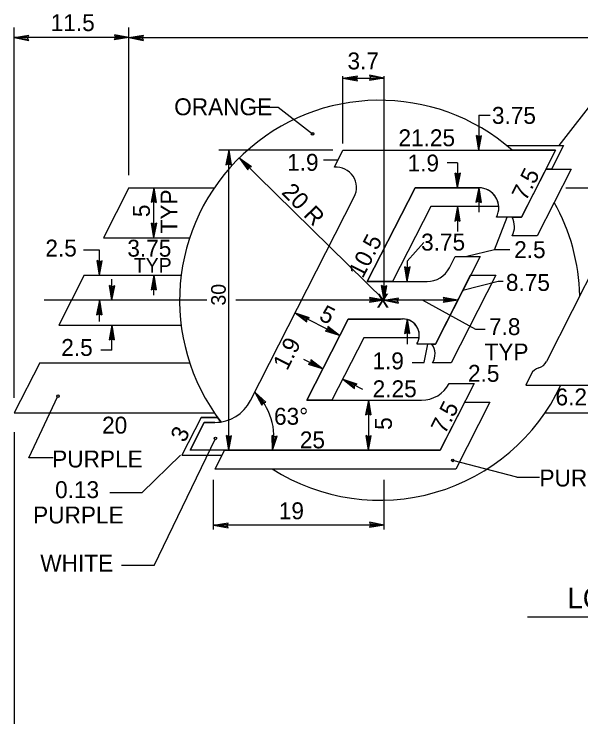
# Model space of a CAD drawing. Extents: x 10268197 to 10269179, y 2141503 to 2142677.
# Drawn here: x 10268597.1 to 10268620.55, y 2142238.8 to 2142268.18 of the extents above; entities that cross this region are included whole.
import ezdxf

# ---------------------------------------------------------------- set-up
doc = ezdxf.new("R2010")
doc.units = 0
for name, color, linetype in [('1', 7, 'Continuous'), ('2', 7, 'Continuous'), ('21', 7, 'Continuous'), ('3', 7, 'Continuous')]:
    doc.layers.add(name, color=color, linetype=linetype)

msp = doc.modelspace()

# ---------------------------------------------------------------- linework, layer by layer
at = {"layer": '1'}
for p, q in [((10268597.104, 2142252.29), (10268597.104, 2142267.627)), ((10268601.85, 2142261.513), (10268601.85, 2142267.627)), ((10268601.85, 2142267.213), (10268597.104, 2142267.213)), ((10268601.85, 2142267.213), (10268602.455, 2142267.309)), ((10268601.85, 2142267.213), (10268602.43, 2142267.254)), ((10268601.85, 2142267.213), (10268627.004, 2142267.213)), ((10268601.85, 2142267.213), (10268602.452, 2142267.097)), ((10268601.85, 2142267.213), (10268602.429, 2142267.153)), ((10268602.408, 2142267.204), (10268602.455, 2142267.309)), ((10268602.452, 2142267.097), (10268602.408, 2142267.204)), ((10268610.711, 2142265.538), (10268611.317, 2142265.634)), ((10268610.711, 2142262.832), (10268610.711, 2142265.61)), ((10268610.711, 2142265.538), (10268611.291, 2142265.578)), ((10268610.711, 2142265.538), (10268612.409, 2142265.538)), ((10268610.711, 2142265.538), (10268611.313, 2142265.422)), ((10268610.711, 2142265.538), (10268611.289, 2142265.478)), ((10268611.268, 2142265.528), (10268611.317, 2142265.634)), ((10268611.313, 2142265.422), (10268611.268, 2142265.528)), ((10268612.409, 2142256.338), (10268612.409, 2142265.61)), ((10268619.662, 2142262.748), (10268621.688, 2142265.366)), ((10268607.088, 2142264.329), (10268608.025, 2142264.329)), ((10268608.025, 2142264.329), (10268609.453, 2142263.226)), ((10268616.331, 2142263.999), (10268616.331, 2142262.548)), ((10268616.331, 2142263.999), (10268616.799, 2142263.999)), ((10268616.331, 2142262.548), (10268616.235, 2142263.154)), ((10268616.341, 2142263.105), (10268616.235, 2142263.154)), ((10268616.331, 2142262.548), (10268616.291, 2142263.128)), ((10268616.331, 2142262.548), (10268616.448, 2142263.149)), ((10268616.331, 2142262.548), (10268616.392, 2142263.127)), ((10268616.448, 2142263.149), (10268616.341, 2142263.105)), ((10268610.297, 2142262.548), (10268605.572, 2142262.548)), ((10268605.985, 2142262.548), (10268605.869, 2142261.947)), ((10268605.985, 2142262.548), (10268605.925, 2142261.97)), ((10268605.985, 2142250.127), (10268605.985, 2142262.548)), ((10268605.985, 2142262.548), (10268606.081, 2142261.942)), ((10268605.985, 2142262.548), (10268606.026, 2142261.968)), ((10268612.409, 2142256.338), (10268606.421, 2142262.237)), ((10268606.421, 2142262.237), (10268606.919, 2142261.881)), ((10268606.421, 2142262.237), (10268606.767, 2142261.732)), ((10268606.421, 2142262.237), (10268606.791, 2142261.788)), ((10268606.421, 2142262.237), (10268606.862, 2142261.859)), ((10268605.869, 2142261.947), (10268605.976, 2142261.991)), ((10268605.976, 2142261.991), (10268606.081, 2142261.942)), ((10268610.5, 2142262.134), (10268609.911, 2142262.134)), ((10268615.452, 2142262.03), (10268615.021, 2142262.03)), ((10268615.452, 2142262.03), (10268615.452, 2142260.995)), ((10268606.767, 2142261.732), (10268606.811, 2142261.839)), ((10268606.811, 2142261.839), (10268606.919, 2142261.881)), ((10268615.452, 2142260.995), (10268615.356, 2142261.6)), ((10268615.461, 2142261.553), (10268615.356, 2142261.6)), ((10268615.452, 2142260.995), (10268615.569, 2142261.597)), ((10268615.569, 2142261.597), (10268615.461, 2142261.553)), ((10268618.098, 2142259.779), (10268619.114, 2142261.772)), ((10268620.16, 2142261.772), (10268618.749, 2142259.005)), ((10268619.114, 2142261.772), (10268620.16, 2142261.772)), ((10268615.452, 2142260.995), (10268615.411, 2142261.575)), ((10268615.452, 2142260.995), (10268615.512, 2142261.574)), ((10268602.886, 2142260.995), (10268602.769, 2142260.394)), ((10268602.886, 2142260.995), (10268602.825, 2142260.417)), ((10268602.886, 2142258.925), (10268602.886, 2142260.995)), ((10268602.886, 2142260.995), (10268602.982, 2142260.39)), ((10268602.886, 2142260.995), (10268602.926, 2142260.416)), ((10268611.715, 2142257.114), (10268613.693, 2142260.995)), ((10268613.693, 2142260.995), (10268616.331, 2142260.995)), ((10268616.331, 2142260.995), (10268616.214, 2142260.394)), ((10268616.331, 2142260.995), (10268616.27, 2142260.417)), ((10268616.331, 2142260.995), (10268616.427, 2142260.39)), ((10268616.331, 2142260.995), (10268616.372, 2142260.416)), ((10268616.331, 2142260.995), (10268616.331, 2142259.984)), ((10268602.769, 2142260.394), (10268602.876, 2142260.438)), ((10268602.876, 2142260.438), (10268602.982, 2142260.39)), ((10268616.214, 2142260.394), (10268616.321, 2142260.438)), ((10268616.321, 2142260.438), (10268616.427, 2142260.39)), ((10268614.343, 2142260.219), (10268612.761, 2142257.114)), ((10268617.158, 2142260.219), (10268614.343, 2142260.219)), ((10268615.452, 2142260.219), (10268615.335, 2142259.618)), ((10268615.452, 2142260.219), (10268615.391, 2142259.64)), ((10268615.452, 2142260.219), (10268615.452, 2142259.184)), ((10268615.452, 2142260.219), (10268615.548, 2142259.614)), ((10268615.452, 2142260.219), (10268615.493, 2142259.64)), ((10268615.335, 2142259.618), (10268615.443, 2142259.661)), ((10268615.443, 2142259.661), (10268615.548, 2142259.614)), ((10268616.976, 2142258.427), (10268617.507, 2142259.781)), ((10268617.713, 2142259.779), (10268618.098, 2142259.779)), ((10268602.886, 2142258.925), (10268602.789, 2142259.53)), ((10268602.895, 2142259.483), (10268602.789, 2142259.53)), ((10268602.886, 2142258.925), (10268602.844, 2142259.505)), ((10268602.886, 2142258.925), (10268603.002, 2142259.527)), ((10268602.886, 2142258.925), (10268602.946, 2142259.504)), ((10268603.002, 2142259.527), (10268602.895, 2142259.483)), ((10268618.749, 2142259.005), (10268617.714, 2142259.005)), ((10268614.056, 2142258.726), (10268613.374, 2142257.956)), ((10268600.634, 2142258.408), (10268599.978, 2142258.412)), ((10268600.634, 2142257.373), (10268600.634, 2142258.408)), ((10268616.976, 2142258.427), (10268615.837, 2142258.149)), ((10268617.619, 2142258.427), (10268616.976, 2142258.427)), ((10268600.634, 2142257.373), (10268600.538, 2142257.978)), ((10268600.643, 2142257.93), (10268600.538, 2142257.978)), ((10268600.634, 2142257.373), (10268600.593, 2142257.952)), ((10268600.634, 2142257.373), (10268600.75, 2142257.974)), ((10268600.634, 2142257.373), (10268600.694, 2142257.951)), ((10268600.75, 2142257.974), (10268600.643, 2142257.93)), ((10268613.374, 2142257.956), (10268613.374, 2142257.114)), ((10268613.374, 2142257.114), (10268613.277, 2142257.719)), ((10268613.383, 2142257.671), (10268613.277, 2142257.719)), ((10268613.374, 2142257.114), (10268613.333, 2142257.693)), ((10268613.374, 2142257.114), (10268613.49, 2142257.716)), ((10268613.374, 2142257.114), (10268613.434, 2142257.692)), ((10268613.49, 2142257.716), (10268613.383, 2142257.671)), ((10268601.151, 2142256.338), (10268601.151, 2142257.217)), ((10268602.886, 2142257.373), (10268602.769, 2142256.771)), ((10268602.886, 2142257.373), (10268602.825, 2142256.794)), ((10268602.886, 2142256.545), (10268602.886, 2142257.373)), ((10268602.886, 2142257.373), (10268602.982, 2142256.767)), ((10268602.886, 2142257.373), (10268602.926, 2142256.793)), ((10268614.542, 2142254.526), (10268615.993, 2142257.373)), ((10268617.038, 2142257.373), (10268615.192, 2142253.75)), ((10268615.993, 2142257.373), (10268617.038, 2142257.373)), ((10268601.151, 2142256.338), (10268601.055, 2142256.942)), ((10268601.16, 2142256.895), (10268601.055, 2142256.942)), ((10268601.151, 2142256.338), (10268601.111, 2142256.917)), ((10268601.151, 2142256.338), (10268601.268, 2142256.939)), ((10268601.151, 2142256.338), (10268601.212, 2142256.916)), ((10268601.268, 2142256.939), (10268601.16, 2142256.895)), ((10268612.761, 2142257.114), (10268611.715, 2142257.114)), ((10268612.409, 2142256.338), (10268612.312, 2142256.942)), ((10268612.418, 2142256.895), (10268612.312, 2142256.942)), ((10268612.409, 2142256.338), (10268612.368, 2142256.917)), ((10268612.409, 2142256.338), (10268612.525, 2142256.939)), ((10268612.409, 2142256.338), (10268612.469, 2142256.916)), ((10268612.525, 2142256.939), (10268612.418, 2142256.895)), ((10268617.131, 2142257.115), (10268615.668, 2142256.735)), ((10268617.337, 2142257.115), (10268617.131, 2142257.115)), ((10268602.769, 2142256.771), (10268602.876, 2142256.815)), ((10268602.876, 2142256.815), (10268602.982, 2142256.767)), ((10268605.082, 2142256.338), (10268598.348, 2142256.338)), ((10268600.634, 2142256.338), (10268600.517, 2142255.736)), ((10268600.634, 2142256.338), (10268600.573, 2142255.759)), ((10268600.634, 2142255.458), (10268600.634, 2142256.338)), ((10268600.634, 2142256.338), (10268600.73, 2142255.732)), ((10268600.634, 2142256.338), (10268600.674, 2142255.758)), ((10268612.409, 2142256.338), (10268606.276, 2142256.338)), ((10268611.851, 2142256.347), (10268611.803, 2142256.242)), ((10268612.409, 2142256.338), (10268611.803, 2142256.242)), ((10268612.409, 2142256.338), (10268611.807, 2142256.454)), ((10268611.807, 2142256.454), (10268611.851, 2142256.347)), ((10268612.409, 2142256.338), (10268611.829, 2142256.297)), ((10268612.409, 2142256.338), (10268611.83, 2142256.398)), ((10268612.409, 2142256.338), (10268613.013, 2142256.433)), ((10268612.409, 2142256.338), (10268612.988, 2142256.378)), ((10268615.466, 2142256.338), (10268612.409, 2142256.338)), ((10268612.409, 2142256.338), (10268613.01, 2142256.221)), ((10268612.409, 2142256.338), (10268612.987, 2142256.277)), ((10268612.966, 2142256.328), (10268613.013, 2142256.433)), ((10268613.01, 2142256.221), (10268612.966, 2142256.328)), ((10268616.205, 2142255.132), (10268614.001, 2142256.338)), ((10268614.908, 2142256.347), (10268614.86, 2142256.242)), ((10268615.466, 2142256.338), (10268614.86, 2142256.242)), ((10268615.466, 2142256.338), (10268614.864, 2142256.454)), ((10268614.864, 2142256.454), (10268614.908, 2142256.347)), ((10268615.466, 2142256.338), (10268614.886, 2142256.297)), ((10268615.466, 2142256.338), (10268614.887, 2142256.398)), ((10268600.517, 2142255.736), (10268600.624, 2142255.78)), ((10268600.624, 2142255.78), (10268600.73, 2142255.732)), ((10268610.574, 2142254.873), (10268608.729, 2142255.814)), ((10268608.729, 2142255.814), (10268609.312, 2142255.624)), ((10268608.729, 2142255.814), (10268609.213, 2142255.437)), ((10268608.729, 2142255.814), (10268609.217, 2142255.498)), ((10268608.729, 2142255.814), (10268609.264, 2142255.587)), ((10268609.21, 2142252.198), (10268610.925, 2142255.561)), ((10268609.213, 2142255.437), (10268609.222, 2142255.552)), ((10268609.222, 2142255.552), (10268609.312, 2142255.624)), ((10268610.925, 2142255.561), (10268613.098, 2142255.554)), ((10268613.374, 2142255.561), (10268613.257, 2142254.96)), ((10268613.374, 2142255.561), (10268613.313, 2142254.983)), ((10268613.374, 2142255.561), (10268613.47, 2142254.956)), ((10268613.374, 2142255.561), (10268613.414, 2142254.982)), ((10268613.374, 2142255.561), (10268613.374, 2142254.526)), ((10268601.151, 2142255.302), (10268601.035, 2142254.701)), ((10268601.151, 2142255.302), (10268601.091, 2142254.724)), ((10268601.151, 2142254.267), (10268601.151, 2142255.302)), ((10268601.151, 2142255.302), (10268601.247, 2142254.697)), ((10268601.151, 2142255.302), (10268601.192, 2142254.723)), ((10268610.082, 2142255.135), (10268609.991, 2142255.063)), ((10268610.091, 2142255.251), (10268610.082, 2142255.135)), ((10268610.574, 2142254.873), (10268610.086, 2142255.19)), ((10268610.574, 2142254.873), (10268610.091, 2142255.251)), ((10268616.59, 2142255.132), (10268616.205, 2142255.132)), ((10268610.574, 2142254.873), (10268609.991, 2142255.063)), ((10268610.574, 2142254.873), (10268610.039, 2142255.1)), ((10268613.257, 2142254.96), (10268613.364, 2142255.004)), ((10268613.364, 2142255.004), (10268613.47, 2142254.956)), ((10268601.035, 2142254.701), (10268601.142, 2142254.745)), ((10268601.142, 2142254.745), (10268601.247, 2142254.697)), ((10268611.573, 2142254.783), (10268610.256, 2142252.198)), ((10268613.859, 2142254.775), (10268611.573, 2142254.783)), ((10268601.151, 2142254.267), (10268600.693, 2142254.271)), ((10268614.065, 2142253.763), (10268614.221, 2142254.526)), ((10268614.379, 2142254.526), (10268614.542, 2142254.526)), ((10268609.869, 2142253.491), (10268609.088, 2142253.889)), ((10268609.377, 2142253.753), (10268609.287, 2142253.68)), ((10268609.869, 2142253.491), (10268609.287, 2142253.68)), ((10268609.869, 2142253.491), (10268609.335, 2142253.718)), ((10268609.387, 2142253.868), (10268609.377, 2142253.753)), ((10268609.869, 2142253.491), (10268609.382, 2142253.807)), ((10268609.869, 2142253.491), (10268609.387, 2142253.868)), ((10268613.57, 2142253.763), (10268614.065, 2142253.763)), ((10268615.192, 2142253.75), (10268614.416, 2142253.75)), ((10268611.532, 2142252.642), (10268610.699, 2142253.067)), ((10268610.699, 2142253.067), (10268611.282, 2142252.878)), ((10268610.699, 2142253.067), (10268611.182, 2142252.69)), ((10268610.699, 2142253.067), (10268611.187, 2142252.75)), ((10268610.699, 2142253.067), (10268611.234, 2142252.841)), ((10268611.182, 2142252.69), (10268611.191, 2142252.806)), ((10268611.191, 2142252.806), (10268611.282, 2142252.878)), ((10268607.057, 2142252.532), (10268607.514, 2142252.123)), ((10268607.057, 2142252.532), (10268607.347, 2142251.992)), ((10268607.057, 2142252.532), (10268607.376, 2142252.045)), ((10268607.057, 2142252.532), (10268607.455, 2142252.108)), ((10268597.71, 2142249.815), (10268598.915, 2142252.365)), ((10268610.256, 2142252.198), (10268609.21, 2142252.198)), ((10268611.763, 2142252.198), (10268611.646, 2142251.596)), ((10268611.763, 2142252.198), (10268611.702, 2142251.619)), ((10268611.763, 2142252.198), (10268611.763, 2142250.127)), ((10268611.763, 2142252.198), (10268611.859, 2142251.592)), ((10268611.763, 2142252.198), (10268611.803, 2142251.617)), ((10268607.347, 2142251.992), (10268607.402, 2142252.094)), ((10268607.402, 2142252.094), (10268607.514, 2142252.123)), ((10268614.734, 2142250.127), (10268615.748, 2142252.117)), ((10268616.794, 2142252.117), (10268615.383, 2142249.35)), ((10268615.748, 2142252.117), (10268616.794, 2142252.117)), ((10268611.646, 2142251.596), (10268611.754, 2142251.64)), ((10268611.754, 2142251.64), (10268611.859, 2142251.592)), ((10268597.104, 2142250.878), (10268597.104, 2142238.799)), ((10268605.985, 2142250.127), (10268605.89, 2142250.732)), ((10268605.995, 2142250.684), (10268605.89, 2142250.732)), ((10268605.985, 2142250.127), (10268606.102, 2142250.728)), ((10268606.102, 2142250.728), (10268605.995, 2142250.684)), ((10268607.798, 2142250.127), (10268607.776, 2142250.739)), ((10268607.875, 2142250.679), (10268607.776, 2142250.739)), ((10268611.763, 2142250.127), (10268611.666, 2142250.732)), ((10268611.772, 2142250.684), (10268611.666, 2142250.732)), ((10268611.763, 2142250.127), (10268611.879, 2142250.728)), ((10268611.879, 2142250.728), (10268611.772, 2142250.684)), ((10268602.896, 2142245.358), (10268605.432, 2142250.615)), ((10268605.985, 2142250.127), (10268605.945, 2142250.707)), ((10268605.985, 2142250.127), (10268606.046, 2142250.705)), ((10268607.798, 2142250.127), (10268607.987, 2142250.71)), ((10268607.798, 2142250.127), (10268607.828, 2142250.707)), ((10268607.798, 2142250.127), (10268607.927, 2142250.694)), ((10268607.987, 2142250.71), (10268607.875, 2142250.679)), ((10268611.763, 2142250.127), (10268611.722, 2142250.707)), ((10268611.763, 2142250.127), (10268611.823, 2142250.705)), ((10268602.394, 2142248.373), (10268603.989, 2142249.919)), ((10268605.418, 2142249.35), (10268605.814, 2142250.127)), ((10268605.814, 2142250.127), (10268614.734, 2142250.127)), ((10268598.718, 2142249.815), (10268597.71, 2142249.815)), ((10268617.909, 2142249.009), (10268615.251, 2142249.705)), ((10268615.383, 2142249.35), (10268605.418, 2142249.35)), ((10268617.909, 2142249.009), (10268618.846, 2142249.009)), ((10268605.358, 2142246.85), (10268605.358, 2142248.907)), ((10268612.409, 2142246.85), (10268612.409, 2142248.907)), ((10268601.057, 2142248.373), (10268602.394, 2142248.373)), ((10268612.409, 2142247.025), (10268605.358, 2142247.025)), ((10268601.54, 2142245.367), (10268602.896, 2142245.367))]:
    msp.add_line(p, q, dxfattribs=at)
msp.add_lwpolyline([(10268617.472, 2142262.748), (10268619.844, 2142262.748), (10268619.347, 2142261.772), (10268619.114, 2142261.772), (10268619.51, 2142262.548), (10268617.708, 2142262.548)], close=True, dxfattribs=at)
for centre in [(10268609.453, 2142263.227), (10268598.915, 2142252.365), (10268605.432, 2142250.616), (10268615.251, 2142249.705)]:
    msp.add_circle(centre, 0.0518, dxfattribs=at)
for centre, radius, start, end in [((10268616.331, 2142260.168), 0.828, 3.5833, 90), ((10268616.981, 2142259.391), 0.828, 332.2089, 27.9127), ((10268613.196, 2142254.889), 0.673, 350.3502, 98.3344), ((10268613.849, 2142254.112), 0.673, 327.421, 37.9799), ((10268605.266, 2142250.664), 2.588, 348.03, 46.2026)]:
    msp.add_arc(centre, radius, start, end, dxfattribs=at)
at = {"layer": '2'}
for p, q in [((10268610.358, 2142261.854), (10268610.711, 2142262.548)), ((10268610.711, 2142262.548), (10268619.51, 2142262.548)), ((10268617.472, 2142262.748), (10268619.844, 2142262.748)), ((10268619.51, 2142262.548), (10268618.1, 2142259.781)), ((10268619.844, 2142262.748), (10268619.347, 2142261.772)), ((10268618.098, 2142259.779), (10268619.114, 2142261.772)), ((10268620.16, 2142261.772), (10268618.749, 2142259.005)), ((10268619.114, 2142261.772), (10268620.16, 2142261.772)), ((10268601.85, 2142260.995), (10268600.796, 2142258.925)), ((10268601.85, 2142260.995), (10268605.384, 2142260.995)), ((10268613.693, 2142260.995), (10268611.715, 2142257.114)), ((10268611.715, 2142257.114), (10268613.693, 2142260.995)), ((10268616.331, 2142260.995), (10268613.693, 2142260.995)), ((10268613.693, 2142260.995), (10268616.331, 2142260.995)), ((10268619.941, 2142260.995), (10268649.465, 2142260.995)), ((10268606.88, 2142252.184), (10268611.175, 2142260.614)), ((10268614.343, 2142260.219), (10268612.761, 2142257.114)), ((10268617.158, 2142260.219), (10268614.343, 2142260.219)), ((10268618.1, 2142259.781), (10268617.064, 2142259.781)), ((10268617.713, 2142259.779), (10268618.098, 2142259.779)), ((10268618.749, 2142259.005), (10268617.714, 2142259.005)), ((10268600.796, 2142258.925), (10268604.365, 2142258.925)), ((10268621.696, 2142258.871), (10268619.134, 2142253.804)), ((10268616.388, 2142258.149), (10268614.542, 2142254.526)), ((10268615.113, 2142257.679), (10268615.353, 2142258.149)), ((10268615.353, 2142258.149), (10268616.388, 2142258.149)), ((10268600.005, 2142257.373), (10268598.95, 2142255.302)), ((10268600.005, 2142257.373), (10268604.015, 2142257.373)), ((10268614.542, 2142254.526), (10268615.993, 2142257.373)), ((10268617.038, 2142257.373), (10268615.192, 2142253.75)), ((10268615.993, 2142257.373), (10268617.038, 2142257.373)), ((10268611.715, 2142257.114), (10268614.191, 2142257.114)), ((10268612.761, 2142257.114), (10268611.715, 2142257.114)), ((10268610.925, 2142255.561), (10268609.21, 2142252.198)), ((10268609.21, 2142252.198), (10268610.925, 2142255.561)), ((10268613.196, 2142255.561), (10268610.925, 2142255.561)), ((10268610.925, 2142255.561), (10268613.098, 2142255.554)), ((10268598.95, 2142255.302), (10268604.015, 2142255.302)), ((10268611.573, 2142254.783), (10268610.256, 2142252.198)), ((10268613.859, 2142254.775), (10268611.573, 2142254.783)), ((10268614.542, 2142254.526), (10268613.763, 2142254.526)), ((10268614.379, 2142254.526), (10268614.542, 2142254.526)), ((10268598.159, 2142253.75), (10268597.104, 2142251.679)), ((10268598.159, 2142253.75), (10268604.365, 2142253.75)), ((10268615.192, 2142253.75), (10268614.416, 2142253.75)), ((10268618.504, 2142253.278), (10268618.272, 2142252.818)), ((10268616.143, 2142252.894), (10268614.734, 2142250.127)), ((10268615.108, 2142252.894), (10268616.143, 2142252.894)), ((10268618.272, 2142252.818), (10268620.859, 2142252.818)), ((10268609.21, 2142252.198), (10268613.96, 2142252.198)), ((10268610.256, 2142252.198), (10268609.21, 2142252.198)), ((10268614.734, 2142250.127), (10268615.748, 2142252.117)), ((10268616.794, 2142252.117), (10268615.383, 2142249.35)), ((10268615.748, 2142252.117), (10268616.794, 2142252.117)), ((10268597.104, 2142251.679), (10268605.384, 2142251.679)), ((10268619.077, 2142251.679), (10268644.718, 2142251.679)), ((10268604.843, 2142251.487), (10268604.045, 2142249.919)), ((10268604.843, 2142251.487), (10268605.519, 2142251.487)), ((10268604.383, 2142250.127), (10268604.97, 2142251.28)), ((10268604.97, 2142251.28), (10268604.383, 2142250.127)), ((10268604.97, 2142251.28), (10268605.405, 2142251.28)), ((10268605.405, 2142251.28), (10268604.97, 2142251.28)), ((10268604.045, 2142249.919), (10268605.708, 2142249.919)), ((10268614.734, 2142250.127), (10268604.383, 2142250.127)), ((10268605.418, 2142249.35), (10268605.814, 2142250.127)), ((10268605.814, 2142250.127), (10268614.734, 2142250.127)), ((10268615.383, 2142249.35), (10268605.418, 2142249.35))]:
    msp.add_line(p, q, dxfattribs=at)
for centre, radius, start, end in [((10268612.231, 2142256.338), 8.281, 48.5904, 217.4725), ((10268610.414, 2142261.002), 0.854, 332.9998, 93.8045), ((10268616.331, 2142260.168), 0.828, 332.2089, 90), ((10268616.331, 2142260.168), 0.828, 3.5833, 90), ((10268612.231, 2142256.338), 8.281, 1.2967, 29.2778), ((10268616.981, 2142259.391), 0.828, 332.2089, 27.9127), ((10268614.191, 2142258.149), 1.035, 270, 332.9883), ((10268613.196, 2142254.889), 0.673, 350.3502, 98.3344), ((10268613.196, 2142254.889), 0.673, 327.421, 90), ((10268613.849, 2142254.112), 0.673, 327.421, 37.9799), ((10268612.231, 2142256.338), 8.281, 237.5383, 334.8493), ((10268613.96, 2142253.491), 1.294, 270, 332.5096), ((10268605.405, 2142252.936), 1.656, 270, 332.9991)]:
    msp.add_arc(centre, radius, start, end, dxfattribs=at)
for centre, start_param, end_param in [((10268618.673, 2142254.041), 0.286787, 1.099486), ((10268618.965, 2142253.041), 3.428379, 4.240701)]:
    msp.add_ellipse(centre, major_axis=(0, -0.521), ratio=0.992614, start_param=start_param, end_param=end_param, dxfattribs=at)
at = {"layer": '21'}
for p, q in [((10268597.104, 2142267.213), (10268597.709, 2142267.309)), ((10268597.104, 2142267.213), (10268597.684, 2142267.254)), ((10268597.104, 2142267.213), (10268597.706, 2142267.097)), ((10268597.104, 2142267.213), (10268597.682, 2142267.153)), ((10268597.661, 2142267.204), (10268597.709, 2142267.309)), ((10268597.706, 2142267.097), (10268597.661, 2142267.204)), ((10268601.293, 2142267.223), (10268601.245, 2142267.117)), ((10268601.85, 2142267.213), (10268601.245, 2142267.117)), ((10268601.85, 2142267.213), (10268601.249, 2142267.33)), ((10268601.249, 2142267.33), (10268601.293, 2142267.223)), ((10268601.85, 2142267.213), (10268601.271, 2142267.173)), ((10268601.85, 2142267.213), (10268601.272, 2142267.274)), ((10268611.851, 2142265.547), (10268611.803, 2142265.442)), ((10268612.409, 2142265.538), (10268611.803, 2142265.442)), ((10268612.409, 2142265.538), (10268611.807, 2142265.654)), ((10268611.807, 2142265.654), (10268611.851, 2142265.547)), ((10268612.409, 2142265.538), (10268611.829, 2142265.497)), ((10268612.409, 2142265.538), (10268611.83, 2142265.598)), ((10268605.358, 2142247.025), (10268605.964, 2142247.122)), ((10268605.358, 2142247.025), (10268605.938, 2142247.066)), ((10268605.358, 2142247.025), (10268605.96, 2142246.909)), ((10268605.358, 2142247.025), (10268605.937, 2142246.965)), ((10268605.916, 2142247.016), (10268605.964, 2142247.122)), ((10268605.96, 2142246.909), (10268605.916, 2142247.016)), ((10268611.851, 2142247.034), (10268611.803, 2142246.929)), ((10268612.409, 2142247.025), (10268611.803, 2142246.929)), ((10268612.409, 2142247.025), (10268611.807, 2142247.142)), ((10268611.807, 2142247.142), (10268611.851, 2142247.034)), ((10268612.409, 2142247.025), (10268611.829, 2142246.984)), ((10268612.409, 2142247.025), (10268611.83, 2142247.086)), ((10268618.353, 2142243.223), (10268628.215, 2142243.223))]:
    msp.add_line(p, q, dxfattribs=at)
at = {"layer": '3'}
msp.add_lwpolyline([(10268605.519, 2142251.487), (10268604.843, 2142251.487), (10268604.045, 2142249.919), (10268605.708, 2142249.919), (10268605.814, 2142250.127), (10268604.383, 2142250.127), (10268604.97, 2142251.28), (10268605.405, 2142251.28), (10268605.659, 2142251.3)], close=True, dxfattribs=at)

# ---------------------------------------------------------------- texts
at = {"layer": '1'}
for s, height, p in [('11.5', 0.7, (10268598.616, 2142267.483)), ('3.7', 0.7, (10268610.898, 2142265.897)), ('ORANGE', 0.7, (10268603.726, 2142263.999)), ('3.75', 0.7, (10268616.875, 2142263.642)), ('21.25', 0.7, (10268613.007, 2142262.715)), ('1.9', 0.7, (10268608.4, 2142261.699)), ('1.9', 0.7, (10268613.384, 2142261.669)), ('3.75', 0.7, (10268613.945, 2142258.395)), ('2.5', 0.7, (10268598.394, 2142258.148)), ('3.75', 0.7, (10268601.786, 2142258.143)), ('2.5', 0.7, (10268617.796, 2142258.083)), ('TYP', 0.6037, (10268602.051, 2142257.483)), ('8.75', 0.7, (10268617.455, 2142256.724)), ('x', 0.755, (10268612.109, 2142256.037)), ('7.8', 0.7, (10268616.755, 2142254.895)), ('2.5', 0.7, (10268599.052, 2142254.033)), ('TYP', 0.7, (10268616.57, 2142253.845)), ('1.9', 0.7, (10268611.931, 2142253.478)), ('2.5', 0.7, (10268615.886, 2142252.961)), ('2.25', 0.7, (10268611.94, 2142252.321)), ('6.25', 0.7, (10268619.508, 2142251.985)), ('63°', 0.7, (10268607.857, 2142251.182)), ('20', 0.7, (10268600.741, 2142250.816)), ('25', 0.7, (10268608.925, 2142250.206)), ('PURPLE', 0.7, (10268598.676, 2142249.414)), ('PURPLE', 0.7, (10268618.844, 2142248.627)), ('0.13', 0.7, (10268598.796, 2142248.145)), ('PURPLE', 0.7, (10268597.887, 2142247.095)), ('19', 0.7, (10268608.055, 2142247.269)), ('WHITE', 0.7, (10268598.184, 2142245.1)), ('LOGO EP-1', 0.8624, (10268619.996, 2142243.576))]:
    msp.add_text(s, height=height, dxfattribs=at).set_placement(p)
for s, height, rotation, p in [('7.5', 0.7, 63, (10268618.282, 2142260.411)), ('20 R', 0.7, 314.1812, (10268608.135, 2142260.776)), ('TYP', 0.7, 90, (10268603.861, 2142259.105)), ('5', 0.7, 90, (10268602.72, 2142259.781)), ('10.5', 0.7, 63.0402, (10268611.53, 2142257.21)), ('30', 0.6037, 90, (10268605.859, 2142256.116)), ('5', 0.7, 332.9866, (10268609.677, 2142255.546)), ('1.9', 0.7, 63.0402, (10268608.401, 2142253.397)), ('7.5', 0.7, 63, (10268614.935, 2142250.761)), ('5', 0.7, 90, (10268612.735, 2142250.97)), ('3', 0.7, 63, (10268604.159, 2142250.413))]:
    msp.add_text(s, height=height, rotation=rotation, dxfattribs=at).set_placement(p)

doc.saveas('drawing.dxf')
